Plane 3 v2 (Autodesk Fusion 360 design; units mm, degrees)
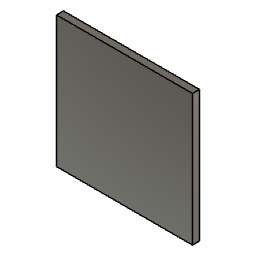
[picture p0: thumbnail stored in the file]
sketch "Sketch1" plane through (0, 0, 0) normal (0, 1, 0) x axis (1, 0, 0)
  line L1 (194.37, 0) -> (0, 0)
  line L2 (194.37, -187.57) -> (194.37, 0)
  line L3 (0, -187.57) -> (194.37, -187.57)
  line L4 (0, 0) -> (0, -187.57)
  point P1 (0, 0)
  point P2 (0, 0)
  point P3 (194.37, 0)
  point P5 (0, -187.57)
  horizontal L1
  vertical L2
  horizontal L3
  vertical L4
  coincident P1 P2
  dimension "d1" distance P2 P3 = 194.37
  dimension "d2" distance P2 P5 = 187.57
extrude "Extrude1" new body sketch "Sketch1" along normal blind 10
